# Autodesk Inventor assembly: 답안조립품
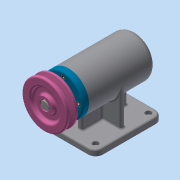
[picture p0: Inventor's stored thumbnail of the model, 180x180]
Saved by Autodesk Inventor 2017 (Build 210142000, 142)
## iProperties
Part Number: 답안조립품
Material: 일반
Document SubType Name: Assembly
Designer: mrc
Author: mrc
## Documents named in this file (12)
- C:\Users\mrc\Desktop\701004V1021\답안조립품.iam
- C:\Users\mrc\Desktop\701004V1021\본체.ipt
- C:\Users\mrc\Desktop\701004V1021\V벨트풀리.ipt
- C:\Users\mrc\Desktop\701004V1021\멈춤나사 M3.ipt
- C:\Users\mrc\Desktop\701004V1021\베어링 6004.ipt
- C:\Users\mrc\Desktop\701004V1021\베어링 51202.ipt
- C:\Users\mrc\Desktop\701004V1021\볼트 M4.ipt
- C:\Users\mrc\Desktop\701004V1021\어댑터슬리브.ipt
- C:\Users\mrc\Desktop\701004V1021\오일 실.ipt
- C:\Users\mrc\Desktop\701004V1021\축.ipt
- C:\Users\mrc\Desktop\701004V1021\커버.ipt
- C:\Users\mrc\Desktop\701004V1021\키 5 x 5 x 16.ipt
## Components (1 placed, 1 different names)
1. V벨트풀리:1 — 플러쉬:1
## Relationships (1: Flush 1)
- 플러쉬:1 [Flush]: V벨트풀리:1
